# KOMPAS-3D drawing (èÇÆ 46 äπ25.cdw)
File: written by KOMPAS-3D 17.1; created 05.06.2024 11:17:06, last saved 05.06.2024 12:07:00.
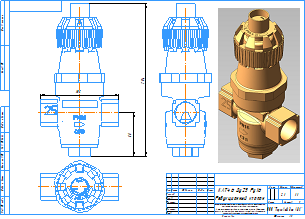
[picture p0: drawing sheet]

Sheet 1: A3, landscape

Title block, sheet 1: name: КАТ46 Ду25 Ру16 / Редукционный клапан; material: Внимание! Данный продукт является объектом авторского права ООО «Торговый Дом АДЛ». / Запрещается изменение, копирование, распространение / (в том числе путем копирования на другие сайты и ресурсы в Интернете) / или любое иное использование информации и объектов без предварительного / согласия правообладателя (ООО «Торговый Дом АДЛ»).; mass: 2,1; sheets: 1; organisation: ООО "Торговый дом АДЛ"; sheet format: A3; stored path: C:\Users\klav\Desktop\Модели\0 КАТ\КАТ 46\KOMPAS 3D\КАТ 46 Ду25.cdw

Views: Вид 1, Спереди, Проекционный вид 2
Referenced files in C:\Users\klav\Desktop\Модели\0 КАТ\КАТ 46\KOMPAS 3D\: КАТ 46 Ду25.m3d
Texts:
  Клочков АВ
  ООО АДЛ Групп
  КАТ 46 Ду25
Dimensions and other numbers on the sheet: 58; 204; 105; 1:1; 1; 2,1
